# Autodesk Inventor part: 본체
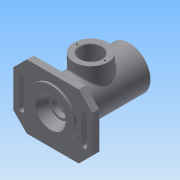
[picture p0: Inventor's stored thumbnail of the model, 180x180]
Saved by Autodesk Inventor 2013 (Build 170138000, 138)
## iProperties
Created: 2017-10
Part Number: 본체
Material: 일반
Document SubType Name: Modeling
Designer: Administrator
Density: 1 g/cm^3
Author: Administrator
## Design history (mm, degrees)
sketch "스케치1"
  geometry: L1 (38, -47)-(-38, -47); L2 (-58, -27)-(-58, 27); L3 (-38, 47)-(38, 47); L4 (58, 27)-(58, -27); L5 (58, -47)-(-58, 47); L6 (-58, -47)-(58, 47); L7 (-58, 27)-(-38, 47); L8 (-58, -27)-(-38, -47); L9 (38, -47)-(58, -27); L10 (58, 27)-(38, 47); 1 further point
  constraints: 20 end point, 8 point on line, 2 midpoint, 2 parallel, 1 horizontal, 1 perpendicular
  dimensions: "d0" = 116 distance of L5.end L6.end; "d2" = 94 distance between parallel lines of L1 L3; "d3" = 20 distance of L2.end L5.end; "d4" = 20 distance of L3.start L5.end (= d3); "d5" = 20 distance of L2.start L6.start (= d3); "d6" = 20 distance of L1.end L6.start (= d5); "d7" = 20 distance of L1.start L5.start (= d3); "d8" = 20 distance of L4.end L5.start (= d7); "d9" = 20 distance of L4.start L6.end (= d3); "d10" = 20 distance of L3.end L6.end (= d9)
extrude "돌출1" new body sketch "스케치1" distance "d11" = 10; taper "d12" = 0 deg
sketch "스케치2"
  geometry: C1 r 35 at (0, 0); 1 further point
  constraints: 1 centre point, 1 coincident
  dimensions: "d13" = 70 diameter of C1
extrude "돌출2" join sketch "스케치2" distance "d15" = 3; taper "d16" = 0 deg
sketch "스케치3"
  geometry: L1 (-27, -10)-(27, -10) reference; L2 (0, -10)-(0, -112); L3 (0, -112)-(31, -112); L4 (31, -112)-(31, -10); L5 (31, -10)-(0, -10); 1 further point
  constraints: 8 end point, 2 parallel, 2 perpendicular, 1 midpoint
  dimensions: "d17" = 102 distance of L2.start L2.end; "d19" = 31 distance of L2.end L3.end
revolve "회전1" sketch "스케치3" stored, may be unused: angle "d20" = 90 deg
sketch "스케치4"
  geometry: L1 (-42, -20)-(-42, 20); L2 (-50, 20)-(-50, -20); L3 (-50, -20)-(-42, 20); L4 (-42, -20)-(-50, 20); C1 r 35 at (0, 0) reference; A1 r 4 centre (-46, 20) between (-42, 20) and (-50, 20); A2 r 4 centre (-46, -20) between (-50, -20) and (-42, -20); 4 further points
  constraints: 8 end point, 4 midpoint, 4 point on circle, 2 centre point, 2 tangent, 1 coincident, 1 horizontal alignment, 1 parallel, 1 vertical alignment
  dimensions: "d22" = 8 distance of L1.end L2.start; "d24" = 40 distance of L2.start L2.end; "d27" = 4 radius of A1; "d28" = 4 radius of A2; "d29" = 46 distance of C1.centre point (-46, 0)
extrude "돌출3" cut sketch "스케치4" stored distance "d30" = 3; taper "d31" = 0 deg
node "작업 평면1"
sketch "스케치5"
  geometry: L1 (38, 0)-(-38, 0) reference; L2 (-31, -112)-(31, -112) reference; C1 r 25 at (0, -56); 2 further points
  constraints: 1 centre point, 1 midpoint, 1 vertical alignment
  dimensions: "d33" = 50 diameter of C1; "d35" = 56 distance from line of L2 C1.centre
extrude "돌출4" join sketch "스케치5" stored distance "d36" = 3; taper "d37" = 0 deg
sketch "스케치6"
  geometry: L1 (22, 3)-(16, -11); L2 (16, -11)-(12.904, -11); L3 (12.5, -11.7)-(12.5, -18); L4 (12.2, -18.3)-(10, -18.3); L5 (10, -18.3)-(10, -21); L6 (10, -21)-(13.5, -21); L7 (16.5, -24)-(16.5, -26); L8 (16.5, -26)-(17.2, -26); L9 (17.5, -26.3)-(17.5, -37); L10 (17.5, -37)-(23, -37); L11 (26, -40)-(26, -72); L12 (23, -75)-(17.5, -75); L13 (17.5, -75)-(17.5, -86); L14 (17.5, -86)-(18.5, -86); L15 (18.5, -86)-(18.5, -87.75); L16 (18.5, -87.75)-(17.5, -87.75); L17 (17.5, -87.75)-(17.5, -91); L18 (17.5, -91)-(20, -91); L19 (20, -91)-(20, -100); L20 (20, -100)-(24, -100); L21 (24, -100)-(24, -103); L22 (24, -103)-(21, -103); L23 (21, -103)-(21, -112); L24 (21, -112)-(0, -112); L25 (0, -112)-(0, 3); L26 (0, 3)-(22, 3); L27 (35, 3)-(-35, 3) reference; L28 (12.5, -11.7)-(12.904, -11); A1 r 3 centre (23, -72) between (23, -75) and (26, -72); A2 r 3 centre (23, -40) between (26, -40) and (23, -37); A3 r 0.3 centre (17.2, -26.3) between (17.5, -26.3) and (17.2, -26); A4 r 3 centre (13.5, -24) between (16.5, -24) and (13.5, -21); A5 r 0.3 centre (12.2, -18) between (12.2, -18.3) and (12.5, -18); 6 further points
  constraints: 54 end point, 23 perpendicular, 10 point on circle, 10 point on line, 10 tangent, 5 centre point, 3 equal radius, 2 horizontal, 1 collinear, 1 vertical alignment
  dimensions: "d38" = 22 distance of L25.end L1.start; "d40" = 14 vertical distance of L1.start L1.end; "d41" = 16 distance from line of L25 L1.end; "d42" = 12.5 distance between parallel lines of L25 L3; "d43" = 10 distance between parallel lines of L25 L5; "d44" = 16.5 distance between parallel lines of L25 L7; "d45" = 17.5 distance between parallel lines of L25 L9; "d46" = 26 distance between parallel lines of L25 L11; "d47" = 17.5 distance between parallel lines of L25 L13; "d48" = 18.5 distance between parallel lines of L25 L15; "d49" = 17.5 distance between parallel lines of L25 L17; "d51" = 20 distance between parallel lines of L25 L19; "d52" = 24 distance between parallel lines of L25 L21; "d53" = 21 distance between parallel lines of L25 L23; "d54" = 7.3 distance of point (12.5, -11) point (12.5, -18.3); "d55" = 2.7 distance of L4.end L5.end; "d56" = 5 distance of point (16.5, -21) L7.end; "d57" = 115 distance of L24.end L25.end; "d58" = 9 distance of L22.end L23.end; "d59" = 3 distance of L20.end L21.end; "d60" = 9 distance of L18.end L19.end; "d61" = 3.25 distance of L16.end L17.end; "d62" = 1.75 distance of L14.end L15.end; "d63" = 11 distance of L12.end L13.end; "d64" = 38 distance of point (26, -37) point (26, -75); "d65" = 3 radius of A1; "d66" = 0.3 radius of A3; "d67" = 0.7 distance of L3.start point (12.5, -11); "d68" = 30 deg angle of L3 L28
revolve "회전2" sketch "스케치6" stored, may be unused: angle "d69" = 90 deg
chamfer "모따기1" distance "d70" = 1; stored, may be unused: second distance "d71" = 2, angle "d72" = 45 deg
sketch "스케치7"
  geometry: C1 r 25 at (0, 0) reference; C2 r 16 at (0, 0); 1 further point
  constraints: 1 centre point, 1 concentric
  dimensions: "d73" = 32 diameter of C2
extrude "돌출5" cut sketch "스케치7" distance "d75" = 40; taper "d76" = 0 deg
chamfer "모따기2" distance "d77" = 1; stored, may be unused: second distance "d78" = 2, angle "d79" = 45 deg
sketch "스케치8" dims "d80" = 41
  geometry: C1 r 25 at (0, 0) reference; C2 r 17 at (0, 0) reference; 3 further points
  constraints: 2 horizontal alignment, 1 coincident, 2 other
node "작업 평면2"
sketch "스케치9"
  geometry: L1 (-31, -112)-(31, -112) reference; L2 (47, -31)-(47, -81) reference; 2 further points
  constraints: 1 other
  dimensions: "d94" = 56 distance from line of L1 point (37, -56); "d95" = 10 distance from line of point (37, -56) L2
feature "엠보싱1" sketch "스케치9" dims "d0" = 116, "d2" = 94, "d3" = 20, "d4" = 20 (= d3), "d5" = 20 (= d3), "d6" = 20 (= d5), "d7" = 20 (= d3), "d8" = 20 (= d7), "d9" = 20 (= d3), "d10" = 20 (= d9), "d83" = 0.5, "d84" = 0
hole "구멍1" sketch "스케치8" diameter "d85" = 2.459; stored, may be unused: countersink angle "d89" = 90 deg, drill point angle "d91" = 118 deg; dims "d86" = 6, "d87" = 4, "d88" = 2, "d90" = 8
feature "스레드1" dims "d92" = 10, "d93" = 0
fillet "모깎기1" dims "d96" = 3
node "솔리드1"
mirror "대칭1"
mirror "대칭2"
other parameters: "d32" = 47, "d82" = -86.5
